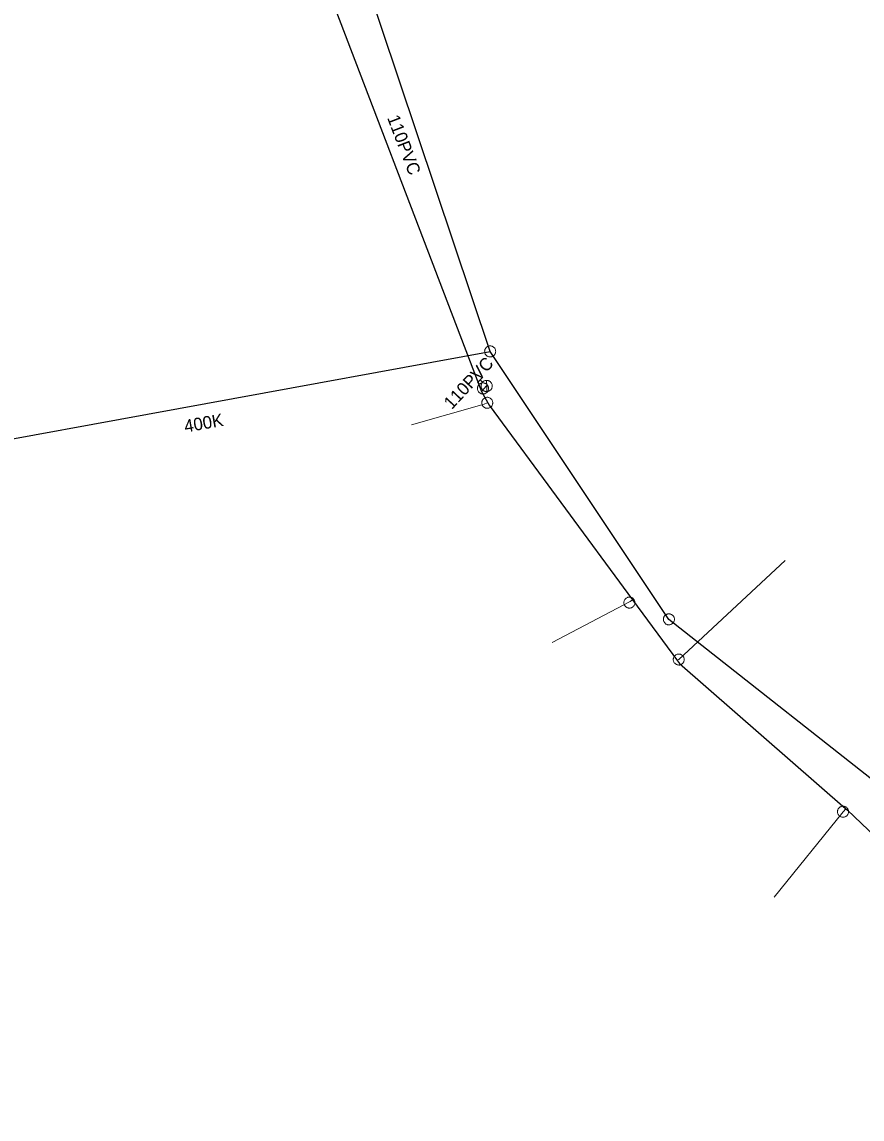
# Model space of a CAD drawing. Extents: x -741806 to -738704, y -1059275 to -1055387.
# Drawn here: x -740162 to -740095.2, y -1056562.9 to -1056475.8 of the extents above; entities that cross this region are included whole.
import ezdxf

# ---------------------------------------------------------------- set-up
doc = ezdxf.new("R2010")
doc.units = 0
doc.header["$LTSCALE"] = 0.4
for name, color, linetype, lineweight in [('2', 7, 'Continuous', 25), ('21', 7, 'Continuous', 13), ('3', 7, 'Continuous', 13), ('50', 7, 'Continuous', 13), ('51', 7, 'Continuous', 13), ('52', 7, 'Continuous', 25)]:
    doc.layers.add(name, color=color, linetype=linetype, lineweight=lineweight)
doc.layers.add('5', color=7, linetype='Continuous')
doc.layers.add('53', color=7, linetype='Continuous')

msp = doc.modelspace()

# ---------------------------------------------------------------- linework, layer by layer
at = {"layer": '2'}
for points in [[(-740124.77, -1056501.96), (-740156.57, -1056407.139), (-740156.993, -1056330.193)], [(-740177.42, -1056561.79), (-740175.219, -1056539.58), (-740169.98, -1056510.23), (-740124.77, -1056501.96)], [(-740070.98, -1056591.81), (-740072.39, -1056553.33), (-740110.57, -1056523.24), (-740124.77, -1056501.96)]]:
    msp.add_lwpolyline(points, dxfattribs=at)
at = {"layer": '21'}
for points in [[(-740124.949, -1056506.027), (-740125, -1056506.04), (-740125.236, -1056506.151), (-740131.013, -1056507.78)], [(-740109.923, -1056526.49), (-740109.789, -1056526.429), (-740101.331, -1056518.56)], [(-740113.46, -1056521.7), (-740113.661, -1056521.814), (-740119.846, -1056525.085)], [(-740096.512, -1056538.29), (-740096.739, -1056538.516), (-740102.202, -1056545.293)]]:
    msp.add_lwpolyline(points, dxfattribs=at)
at = {"layer": '3'}
for points in [[(-740124.339, -1056501.881), (-740124.35, -1056501.837), (-740124.365, -1056501.794), (-740124.384, -1056501.752), (-740124.408, -1056501.714), (-740124.436, -1056501.677), (-740124.467, -1056501.643), (-740124.502, -1056501.614), (-740124.54, -1056501.588), (-740124.58, -1056501.567), (-740124.622, -1056501.549), (-740124.666, -1056501.535), (-740124.711, -1056501.526), (-740124.757, -1056501.524), (-740124.802, -1056501.524), (-740124.848, -1056501.53), (-740124.893, -1056501.54), (-740124.936, -1056501.556), (-740124.977, -1056501.575), (-740125.016, -1056501.6), (-740125.053, -1056501.628), (-740125.086, -1056501.659), (-740125.115, -1056501.693), (-740125.142, -1056501.731), (-740125.164, -1056501.771), (-740125.181, -1056501.814), (-740125.194, -1056501.858), (-740125.203, -1056501.902), (-740125.207, -1056501.948), (-740125.205, -1056501.994), (-740125.199, -1056502.04), (-740125.189, -1056502.084), (-740125.174, -1056502.127), (-740125.154, -1056502.169), (-740125.13, -1056502.208), (-740125.103, -1056502.244), (-740125.071, -1056502.277), (-740125.036, -1056502.307), (-740124.998, -1056502.333), (-740124.959, -1056502.354), (-740124.917, -1056502.372), (-740124.873, -1056502.385), (-740124.827, -1056502.394), (-740124.782, -1056502.398), (-740124.736, -1056502.397), (-740124.691, -1056502.391), (-740124.646, -1056502.381), (-740124.603, -1056502.366), (-740124.562, -1056502.346), (-740124.522, -1056502.321), (-740124.486, -1056502.293), (-740124.453, -1056502.262), (-740124.423, -1056502.228), (-740124.397, -1056502.19), (-740124.375, -1056502.15), (-740124.357, -1056502.107), (-740124.344, -1056502.063), (-740124.336, -1056502.019), (-740124.332, -1056501.972), (-740124.333, -1056501.927), (-740124.338, -1056501.882)], [(-740110.913, -1056522.968), (-740110.939, -1056523.005), (-740110.961, -1056523.045), (-740110.979, -1056523.088), (-740110.993, -1056523.131), (-740111.002, -1056523.176), (-740111.006, -1056523.222), (-740111.005, -1056523.267), (-740111, -1056523.313), (-740110.99, -1056523.357), (-740110.975, -1056523.4), (-740110.956, -1056523.442), (-740110.933, -1056523.482), (-740110.905, -1056523.518), (-740110.875, -1056523.552), (-740110.84, -1056523.582), (-740110.802, -1056523.609), (-740110.762, -1056523.631), (-740110.721, -1056523.649), (-740110.676, -1056523.663), (-740110.631, -1056523.672), (-740110.586, -1056523.675), (-740110.541, -1056523.675), (-740110.495, -1056523.67), (-740110.45, -1056523.66), (-740110.406, -1056523.645), (-740110.365, -1056523.625), (-740110.326, -1056523.603), (-740110.289, -1056523.575), (-740110.255, -1056523.544), (-740110.225, -1056523.509), (-740110.199, -1056523.472), (-740110.177, -1056523.433), (-740110.158, -1056523.39), (-740110.145, -1056523.345), (-740110.136, -1056523.302), (-740110.131, -1056523.256), (-740110.133, -1056523.21), (-740110.138, -1056523.164), (-740110.148, -1056523.12), (-740110.163, -1056523.077), (-740110.182, -1056523.035), (-740110.205, -1056522.995), (-740110.232, -1056522.958), (-740110.263, -1056522.925), (-740110.298, -1056522.895), (-740110.335, -1056522.868), (-740110.375, -1056522.846), (-740110.417, -1056522.828), (-740110.461, -1056522.815), (-740110.507, -1056522.806), (-740110.552, -1056522.802), (-740110.598, -1056522.802), (-740110.643, -1056522.808), (-740110.688, -1056522.817), (-740110.731, -1056522.833), (-740110.773, -1056522.852), (-740110.812, -1056522.875), (-740110.849, -1056522.903), (-740110.882, -1056522.934), (-740110.913, -1056522.967)]]:
    msp.add_lwpolyline(points, dxfattribs=at)
at = {"layer": '50'}
for p, q in [((-740125.339, -1056503.999), (-740125.551, -1056504.221)), ((-740125.764, -1056504.444), (-740125.551, -1056504.221)), ((-740125.37, -1056504.394), (-740125.551, -1056504.221)), ((-740125.046, -1056504.703), (-740125.054, -1056504.259)), ((-740125.046, -1056504.703), (-740125.036, -1056505.151))]:
    msp.add_line(p, q, dxfattribs=at)
msp.add_lwpolyline([(-740124.737, -1056504.384), (-740124.774, -1056504.353), (-740124.811, -1056504.325), (-740124.853, -1056504.302), (-740124.896, -1056504.285), (-740124.938, -1056504.271), (-740124.986, -1056504.262), (-740125.031, -1056504.259), (-740125.08, -1056504.258), (-740125.125, -1056504.263), (-740125.17, -1056504.275), (-740125.215, -1056504.29), (-740125.258, -1056504.308), (-740125.297, -1056504.334), (-740125.335, -1056504.362), (-740125.369, -1056504.393), (-740125.398, -1056504.428), (-740125.426, -1056504.464), (-740125.448, -1056504.507), (-740125.466, -1056504.55), (-740125.481, -1056504.596), (-740125.489, -1056504.64), (-740125.494, -1056504.687), (-740125.493, -1056504.734), (-740125.487, -1056504.779), (-740125.477, -1056504.826), (-740125.463, -1056504.87), (-740125.443, -1056504.912), (-740125.419, -1056504.954), (-740125.389, -1056504.989), (-740125.36, -1056505.025), (-740125.323, -1056505.056), (-740125.285, -1056505.082), (-740125.246, -1056505.104), (-740125.202, -1056505.124), (-740125.157, -1056505.137), (-740125.111, -1056505.147), (-740125.065, -1056505.149), (-740125.018, -1056505.15), (-740124.97, -1056505.144), (-740124.926, -1056505.133), (-740124.881, -1056505.117), (-740124.839, -1056505.097), (-740124.8, -1056505.075), (-740124.76, -1056505.046), (-740124.726, -1056505.014), (-740124.696, -1056504.979), (-740124.67, -1056504.94), (-740124.646, -1056504.899), (-740124.628, -1056504.857), (-740124.614, -1056504.811), (-740124.606, -1056504.767), (-740124.601, -1056504.719), (-740124.602, -1056504.674), (-740124.607, -1056504.628), (-740124.62, -1056504.582), (-740124.632, -1056504.537), (-740124.652, -1056504.494), (-740124.678, -1056504.456), (-740124.705, -1056504.418)], close=True, dxfattribs=at)
at = {"layer": '51'}
for points in [[(-740124.902, -1056504.899), (-740124.904, -1056504.854), (-740124.912, -1056504.809), (-740124.924, -1056504.764), (-740124.94, -1056504.722), (-740124.961, -1056504.681), (-740124.985, -1056504.642), (-740125.015, -1056504.607), (-740125.047, -1056504.574), (-740125.083, -1056504.546), (-740125.12, -1056504.521), (-740125.162, -1056504.5), (-740125.205, -1056504.483), (-740125.249, -1056504.471), (-740125.294, -1056504.464), (-740125.34, -1056504.462), (-740125.386, -1056504.464), (-740125.431, -1056504.471), (-740125.475, -1056504.483), (-740125.517, -1056504.5), (-740125.559, -1056504.521), (-740125.597, -1056504.546), (-740125.632, -1056504.574), (-740125.664, -1056504.607), (-740125.694, -1056504.642), (-740125.718, -1056504.681), (-740125.74, -1056504.722), (-740125.755, -1056504.764), (-740125.767, -1056504.809), (-740125.775, -1056504.854), (-740125.777, -1056504.9), (-740125.775, -1056504.945), (-740125.767, -1056504.99), (-740125.755, -1056505.035), (-740125.74, -1056505.077), (-740125.718, -1056505.118), (-740125.694, -1056505.157), (-740125.664, -1056505.192), (-740125.632, -1056505.225), (-740125.597, -1056505.253), (-740125.559, -1056505.278), (-740125.517, -1056505.299), (-740125.475, -1056505.316), (-740125.431, -1056505.327), (-740125.386, -1056505.335), (-740125.34, -1056505.337), (-740125.294, -1056505.335), (-740125.249, -1056505.327), (-740125.205, -1056505.316), (-740125.162, -1056505.299), (-740125.12, -1056505.278), (-740125.083, -1056505.253), (-740125.047, -1056505.225), (-740125.015, -1056505.192), (-740124.985, -1056505.157), (-740124.961, -1056505.118), (-740124.94, -1056505.077), (-740124.924, -1056505.035), (-740124.912, -1056504.99), (-740124.904, -1056504.945), (-740124.902, -1056504.9)], [(-740124.563, -1056506.04), (-740124.565, -1056505.995), (-740124.572, -1056505.95), (-740124.584, -1056505.905), (-740124.6, -1056505.863), (-740124.621, -1056505.822), (-740124.646, -1056505.783), (-740124.675, -1056505.748), (-740124.707, -1056505.715), (-740124.743, -1056505.687), (-740124.781, -1056505.662), (-740124.822, -1056505.641), (-740124.865, -1056505.624), (-740124.909, -1056505.612), (-740124.954, -1056505.605), (-740125, -1056505.603), (-740125.046, -1056505.605), (-740125.091, -1056505.612), (-740125.135, -1056505.624), (-740125.178, -1056505.641), (-740125.219, -1056505.662), (-740125.257, -1056505.687), (-740125.293, -1056505.715), (-740125.325, -1056505.748), (-740125.354, -1056505.783), (-740125.379, -1056505.822), (-740125.4, -1056505.863), (-740125.416, -1056505.905), (-740125.428, -1056505.95), (-740125.435, -1056505.995), (-740125.438, -1056506.041), (-740125.435, -1056506.086), (-740125.428, -1056506.131), (-740125.416, -1056506.176), (-740125.4, -1056506.218), (-740125.379, -1056506.259), (-740125.354, -1056506.298), (-740125.325, -1056506.333), (-740125.293, -1056506.366), (-740125.257, -1056506.394), (-740125.219, -1056506.419), (-740125.178, -1056506.44), (-740125.135, -1056506.457), (-740125.091, -1056506.468), (-740125.046, -1056506.476), (-740125, -1056506.478), (-740124.954, -1056506.476), (-740124.909, -1056506.468), (-740124.865, -1056506.457), (-740124.822, -1056506.44), (-740124.781, -1056506.419), (-740124.743, -1056506.394), (-740124.707, -1056506.366), (-740124.675, -1056506.333), (-740124.646, -1056506.298), (-740124.621, -1056506.259), (-740124.6, -1056506.218), (-740124.584, -1056506.176), (-740124.572, -1056506.131), (-740124.565, -1056506.086), (-740124.563, -1056506.041)], [(-740109.39, -1056526.25), (-740109.41, -1056526.209), (-740109.435, -1056526.171), (-740109.464, -1056526.135), (-740109.496, -1056526.103), (-740109.532, -1056526.075), (-740109.571, -1056526.049), (-740109.612, -1056526.029), (-740109.654, -1056526.012), (-740109.699, -1056526.002), (-740109.744, -1056525.994), (-740109.79, -1056525.992), (-740109.836, -1056525.994), (-740109.881, -1056526.001), (-740109.925, -1056526.013), (-740109.968, -1056526.03), (-740110.009, -1056526.051), (-740110.047, -1056526.076), (-740110.082, -1056526.105), (-740110.114, -1056526.138), (-740110.143, -1056526.174), (-740110.167, -1056526.212), (-740110.189, -1056526.253), (-740110.204, -1056526.296), (-740110.217, -1056526.34), (-740110.223, -1056526.386), (-740110.226, -1056526.432), (-740110.223, -1056526.477), (-740110.216, -1056526.522), (-740110.203, -1056526.566), (-740110.187, -1056526.61), (-740110.166, -1056526.649), (-740110.141, -1056526.688), (-740110.112, -1056526.724), (-740110.08, -1056526.755), (-740110.044, -1056526.784), (-740110.005, -1056526.809), (-740109.964, -1056526.829), (-740109.922, -1056526.846), (-740109.877, -1056526.857), (-740109.833, -1056526.864), (-740109.787, -1056526.867), (-740109.74, -1056526.865), (-740109.696, -1056526.857), (-740109.651, -1056526.845), (-740109.609, -1056526.828), (-740109.567, -1056526.808), (-740109.53, -1056526.782), (-740109.494, -1056526.754), (-740109.462, -1056526.721), (-740109.433, -1056526.685), (-740109.409, -1056526.646), (-740109.387, -1056526.606), (-740109.372, -1056526.563), (-740109.36, -1056526.519), (-740109.353, -1056526.473), (-740109.35, -1056526.427), (-740109.353, -1056526.382), (-740109.361, -1056526.336), (-740109.373, -1056526.292), (-740109.389, -1056526.251)], [(-740096.301, -1056538.516), (-740096.303, -1056538.471), (-740096.311, -1056538.426), (-740096.323, -1056538.381), (-740096.338, -1056538.339), (-740096.36, -1056538.298), (-740096.384, -1056538.259), (-740096.414, -1056538.224), (-740096.446, -1056538.191), (-740096.482, -1056538.163), (-740096.519, -1056538.138), (-740096.561, -1056538.117), (-740096.603, -1056538.1), (-740096.647, -1056538.088), (-740096.693, -1056538.081), (-740096.739, -1056538.079), (-740096.784, -1056538.081), (-740096.83, -1056538.088), (-740096.874, -1056538.1), (-740096.916, -1056538.117), (-740096.958, -1056538.138), (-740096.995, -1056538.163), (-740097.031, -1056538.191), (-740097.063, -1056538.224), (-740097.093, -1056538.259), (-740097.117, -1056538.298), (-740097.139, -1056538.339), (-740097.154, -1056538.381), (-740097.166, -1056538.426), (-740097.174, -1056538.471), (-740097.176, -1056538.517), (-740097.174, -1056538.562), (-740097.166, -1056538.607), (-740097.154, -1056538.652), (-740097.139, -1056538.694), (-740097.117, -1056538.735), (-740097.093, -1056538.774), (-740097.063, -1056538.809), (-740097.031, -1056538.842), (-740096.995, -1056538.87), (-740096.958, -1056538.895), (-740096.916, -1056538.916), (-740096.874, -1056538.933), (-740096.83, -1056538.944), (-740096.784, -1056538.952), (-740096.739, -1056538.954), (-740096.693, -1056538.952), (-740096.647, -1056538.944), (-740096.603, -1056538.933), (-740096.561, -1056538.916), (-740096.519, -1056538.895), (-740096.482, -1056538.87), (-740096.446, -1056538.842), (-740096.414, -1056538.809), (-740096.384, -1056538.774), (-740096.36, -1056538.735), (-740096.338, -1056538.694), (-740096.323, -1056538.652), (-740096.311, -1056538.607), (-740096.303, -1056538.562), (-740096.301, -1056538.517)]]:
    msp.add_lwpolyline(points, dxfattribs=at)
msp.add_lwpolyline([(-740114.096, -1056522.112), (-740114.073, -1056522.151), (-740114.046, -1056522.188), (-740114.014, -1056522.222), (-740113.981, -1056522.252), (-740113.943, -1056522.278), (-740113.902, -1056522.301), (-740113.86, -1056522.318), (-740113.817, -1056522.332), (-740113.772, -1056522.34), (-740113.727, -1056522.345), (-740113.68, -1056522.344), (-740113.635, -1056522.339), (-740113.59, -1056522.329), (-740113.547, -1056522.314), (-740113.505, -1056522.294), (-740113.466, -1056522.271), (-740113.429, -1056522.244), (-740113.396, -1056522.213), (-740113.366, -1056522.177), (-740113.339, -1056522.14), (-740113.317, -1056522.1), (-740113.299, -1056522.058), (-740113.286, -1056522.014), (-740113.277, -1056521.97), (-740113.273, -1056521.924), (-740113.273, -1056521.877), (-740113.279, -1056521.833), (-740113.289, -1056521.787), (-740113.304, -1056521.744), (-740113.323, -1056521.702), (-740113.347, -1056521.664), (-740113.374, -1056521.627), (-740113.406, -1056521.593), (-740113.439, -1056521.564), (-740113.477, -1056521.537), (-740113.517, -1056521.514), (-740113.559, -1056521.497), (-740113.603, -1056521.483), (-740113.648, -1056521.475), (-740113.693, -1056521.471), (-740113.739, -1056521.471), (-740113.785, -1056521.476), (-740113.829, -1056521.487), (-740113.873, -1056521.501), (-740113.915, -1056521.521), (-740113.954, -1056521.544), (-740113.99, -1056521.572), (-740114.024, -1056521.603), (-740114.054, -1056521.638), (-740114.081, -1056521.675), (-740114.102, -1056521.715), (-740114.121, -1056521.757), (-740114.134, -1056521.801), (-740114.143, -1056521.846), (-740114.147, -1056521.892), (-740114.147, -1056521.938), (-740114.141, -1056521.982), (-740114.131, -1056522.028), (-740114.116, -1056522.071)], close=True, dxfattribs=at)
at = {"layer": '52'}
msp.add_line((-740125.451, -1056505.135), (-740125.05, -1056504.7), dxfattribs=at)
for points in [[(-740146.392, -1056445.304), (-740139.719, -1056467.8), (-740125.451, -1056505.135)], [(-740125.451, -1056505.135), (-740124.943, -1056506.037), (-740124.842, -1056506.219), (-740113.46, -1056521.7), (-740109.896, -1056526.526), (-740109.734, -1056526.747), (-740096.537, -1056538.268), (-740096.386, -1056538.399), (-740076.747, -1056557.08), (-740076.579, -1056557.304), (-740070.758, -1056565.122), (-740070.765, -1056565.379), (-740071.192, -1056579.166), (-740084.006, -1056600.222), (-740084.563, -1056600.566), (-740103.204, -1056615.655), (-740103.68, -1056615.159)]]:
    msp.add_lwpolyline(points, dxfattribs=at)

# ---------------------------------------------------------------- texts
at = {"layer": '5'}
msp.add_text('400K', height=1, rotation=10, dxfattribs=at).set_placement((-740148.984, -1056508.407))
msp.add_text('400K', height=1, rotation=10, dxfattribs=at).set_placement((-740148.984, -1056508.407))
msp.add_text('400K', height=1, rotation=10, dxfattribs=at).set_placement((-740148.984, -1056508.407))
at = {"layer": '53'}
for rotation, p in [(291, (-740132.969, -1056483.402)), (47, (-740127.823, -1056506.624))]:
    msp.add_text('110PVC', height=1, rotation=rotation, dxfattribs=at).set_placement(p)

doc.saveas('drawing.dxf')
